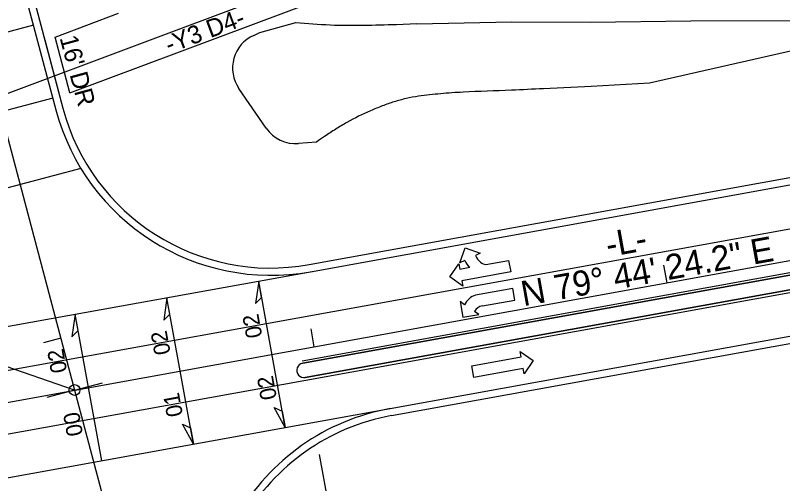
# Model space of a CAD drawing. Extents: x 1616561 to 1622460, y 896726 to 899651.
# Drawn here: x 1620937.7 to 1621151.6, y 898090.7 to 898221.3 of the extents above; entities that cross this region are included whole.
import ezdxf

# ---------------------------------------------------------------- set-up
doc = ezdxf.new("R2010")
doc.units = 0
for name, color, linetype in [('Exist Boundary Study Area', 7, 'Continuous'), ('Old_Level_3', 7, 'Continuous'), ('Prop Conc Drive Radius Type', 7, 'Continuous'), ('Prop Dimension', 7, 'Continuous'), ('Prop Horizontal Alignment Tick Small', 7, 'Continuous'), ('Prop Lane Arrow CELL', 7, 'Continuous'), ('Prop North Arrow NAD83 for Plan Sheets CELL', 7, 'Continuous'), ('Prop Rem of Exist Asph Pvmt', 7, 'Continuous'), ('Prop Shade Medium', 7, 'Continuous'), ('Prop Superelevation  Arrow CELL', 7, 'Continuous'), ('Prop Superelevation Label', 7, 'Continuous'), ('Prop Terminator CELL', 7, 'Continuous'), ('Scratch_Level_1', 7, 'Continuous'), ('Sheet Cutting Line CELL', 7, 'Continuous'), ('Sheet North Arrow CELL', 7, 'Continuous'), ('Sheet Sticker Preliminary CELL', 7, 'Continuous')]:
    doc.layers.add(name, color=color, linetype=linetype)

msp = doc.modelspace()

# ---------------------------------------------------------------- linework, layer by layer
at = {"layer": 'Exist Boundary Study Area'}
for p, q in [((1621017.81, 898124.3), (1621165.41, 898151.01)), ((1621166.12, 898147.08), (1621018.52, 898120.36))]:
    msp.add_line(p, q, dxfattribs=at)
msp.add_arc((1621018.16, 898122.33), 2, 100.2599, 280.2599, dxfattribs=at)
at = {"layer": 'Old_Level_3'}
for p, q in [((1620903.36, 898116.54), (1621261.54, 898181.37)), ((1621017.67, 898125.03), (1621165.28, 898151.75)), ((1620870.63, 898122.84), (1621020.48, 898149.94)), ((1621018.65, 898119.62), (1621166.26, 898146.34)), ((1620891.42, 898096.59), (1621018.65, 898119.62)), ((1620893.24, 898084.73), (1621042.18, 898111.69))]:
    msp.add_line(p, q, dxfattribs=at)
at = {"layer": 'Prop Conc Drive Radius Type'}
msp.add_line((1620945.86, 898214.48), (1620949.99, 898198.94), dxfattribs=at)
at = {"layer": 'Prop Dimension'}
msp.add_line((1621022.41, 898098.88), (1621037.62, 898014.84), dxfattribs=at)
at = {"layer": 'Prop Horizontal Alignment Tick Small'}
for p, q in [((1620941.12, 898232.34), (1620950.92, 898195.46)), ((1621019.59, 898151.82), (1621369.62, 898215.16)), ((1621042.54, 898109.72), (1621403.81, 898175.11))]:
    msp.add_line(p, q, dxfattribs=at)
for centre, start, end in [((1621008.91, 898210.86), 194.8727, 280.2581), ((1621053.22, 898050.68), 100.2599, 199.8507)]:
    msp.add_arc(centre, 60, start, end, dxfattribs=at)
at = {"layer": 'Prop Lane Arrow CELL'}
for p, q in [((1621061.63, 898152.28), (1621063.11, 898156.46)), ((1621063.11, 898156.46), (1621067.29, 898154.98)), ((1621067.29, 898154.98), (1621065.98, 898154.34)), ((1621058.88, 898148.38), (1621061.37, 898152.03)), ((1621061.37, 898152.03), (1621061.64, 898150.56)), ((1621062.98, 898152.93), (1621061.63, 898152.28)), ((1621068.87, 898151.87), (1621075.22, 898153.01)), ((1621075.22, 898153.01), (1621075.8, 898149.77)), ((1621061.64, 898150.56), (1621064.44, 898151.06)), ((1621075.8, 898149.77), (1621062.22, 898147.31)), ((1621062.49, 898145.83), (1621058.88, 898148.38)), ((1621062.22, 898147.31), (1621062.49, 898145.83)), ((1621076.38, 898145.13), (1621065.99, 898143.3)), ((1621076.96, 898141.88), (1621076.38, 898145.13)), ((1621062.96, 898140.63), (1621061.74, 898141.49)), ((1621061.74, 898141.49), (1621062.46, 898137.14)), ((1621067.94, 898140.29), (1621076.96, 898141.88)), ((1621066.9, 898137.88), (1621065.68, 898138.73)), ((1621062.46, 898137.14), (1621066.9, 898137.88)), ((1621064.94, 898123.6), (1621078.72, 898126.09)), ((1621078.72, 898126.09), (1621078.45, 898127.57)), ((1621078.45, 898127.57), (1621082.1, 898125.08)), ((1621065.53, 898120.35), (1621064.94, 898123.6)), ((1621082.1, 898125.08), (1621079.57, 898121.37)), ((1621079.3, 898122.84), (1621065.53, 898120.35)), ((1621079.57, 898121.37), (1621079.3, 898122.84))]:
    msp.add_line(p, q, dxfattribs=at)
for centre, radius, start, end in [((1621070.1, 898156), 4.43, 201.9696, 232.8232), ((1621067.11, 898154.59), 4.43, 201.8508, 232.7294), ((1621069.06, 898154.38), 2.52, 229.3331, 265.6451), ((1621067.67, 898138.34), 5.25, 108.6553, 153.967), ((1621068.5, 898137.08), 3.28, 99.9792, 149.6374)]:
    msp.add_arc(centre, radius, start, end, dxfattribs=at)
at = {"layer": 'Prop North Arrow NAD83 for Plan Sheets CELL'}
for points in [[(1621005.53, 898147.23), (1621004.63, 898140.97), (1621006.35, 898142.67)], [(1620979.94, 898142.59), (1620979.04, 898136.33), (1620980.77, 898138.04)], [(1620954.36, 898137.96), (1620953.46, 898131.7), (1620955.18, 898133.41)], [(1621012.92, 898106.39), (1621009.88, 898111.94), (1621012.1, 898110.94)], [(1620987.34, 898101.76), (1620984.3, 898107.31), (1620986.51, 898106.31)]]:
    msp.add_lwpolyline(points, close=True, dxfattribs=at)
at = {"layer": 'Prop Rem of Exist Asph Pvmt'}
for p, q in [((1621005.86, 898216.5), (1621015.87, 898219.32)), ((1621004.16, 898215.74), (1621005.86, 898216.5)), ((1621158.38, 898212.33), (1621114.48, 898202.38)), ((1621007.59, 898189.88), (1621000, 898200.96)), ((1621021.66, 898185.97), (1621016.66, 898185.56))]:
    msp.add_line(p, q, dxfattribs=at)
for points in [[(1621043.99, 898218.8), (1621049.6, 898219.01), (1621049.67, 898218.95), (1621076, 898219.52), (1621098.08, 898219.37), (1621126.06, 898219.76), (1621167.41, 898219.86), (1621208.75, 898220.77), (1621226.84, 898221.26)], [(1621114.48, 898202.38), (1621098.22, 898201.46), (1621084.97, 898200.86)]]:
    msp.add_lwpolyline(points, dxfattribs=at)
for centre, start, end in [((1621008.25, 898206.61), 114.124, 214.414), ((1621015.84, 898195.53), 214.414, 274.7054)]:
    msp.add_arc(centre, 10, start, end, dxfattribs=at)
for points in [[(1621015.87, 898219.32), (1621025.49, 898218.66), (1621043.99, 898218.8)], [(1621084.97, 898200.86), (1621075.99, 898200.43), (1621062.54, 898199.89), (1621059.42, 898199.71), (1621056.3, 898199.45), (1621053.19, 898199.13), (1621050.08, 898198.74), (1621046.66, 898198.11), (1621043.31, 898197.2), (1621040.01, 898196.05), (1621038.37, 898195.4), (1621036.74, 898194.72), (1621030.16, 898191.46), (1621027.02, 898189.59), (1621023.93, 898187.58), (1621021.66, 898185.97)]]:
    msp.add_spline(points, degree=3, dxfattribs=at)
at = {"layer": 'Prop Shade Medium'}
for p, q in [((1621165.41, 898151.01), (1621017.81, 898124.3)), ((1621018.52, 898120.36), (1621166.12, 898147.08))]:
    msp.add_line(p, q, dxfattribs=at)
msp.add_arc((1621018.16, 898122.33), 2, 100.2599, 280.2599, dxfattribs=at)
at = {"layer": 'Prop Superelevation  Arrow CELL'}
for p, q in [((1621119.43, 898146.76), (1621118.54, 898151.68)), ((1621021.03, 898128.94), (1621020.14, 898133.87)), ((1620950.36, 898131.33), (1620945.53, 898130.04))]:
    msp.add_line(p, q, dxfattribs=at)
at = {"layer": 'Prop Superelevation Label'}
for q in [(1620961.94, 898118.9), (1620946.47, 898114.79)]:
    msp.add_line((1620954.2, 898116.85), q, dxfattribs=at)
at = {"layer": 'Prop Terminator CELL'}
for p, q in [((1620952.89, 898199.71), (1621051.69, 898236.7)), ((1620939.19, 898231.83), (1620948.98, 898194.94)), ((1620948.77, 898215.25), (1620966.48, 898221.88)), ((1620952.89, 898199.71), (1620948.77, 898215.25)), ((1621019.95, 898149.85), (1621369.97, 898213.19)), ((1621042.18, 898111.69), (1621403.45, 898177.08))]:
    msp.add_line(p, q, dxfattribs=at)
for centre, start, end in [((1621008.91, 898210.86), 194.8727, 280.2581), ((1621053.22, 898050.68), 100.2599, 199.8507)]:
    msp.add_arc(centre, 62, start, end, dxfattribs=at)
at = {"layer": 'Sheet Cutting Line CELL'}
for p, q in [((1620903.06, 898309.43), (1620954.2, 898116.85)), ((1620932.52, 898198.49), (1621073, 898251.08)), ((1620889.86, 898105.2), (1621477.45, 898211.56)), ((1620954.2, 898116.85), (1620966.99, 898068.72))]:
    msp.add_line(p, q, dxfattribs=at)
at = {"layer": 'Sheet North Arrow CELL'}
msp.add_line((1620954.2, 898116.85), (1620693.65, 898206.85), dxfattribs=at)
msp.add_circle((1620954.2, 898116.85), 1.5, dxfattribs=at)
at = {"layer": 'Sheet Sticker Preliminary CELL'}
for p, q in [((1620942.71, 898218.57), (1620914.12, 898210.98)), ((1620948.1, 898198.27), (1620918.47, 898190.4)), ((1620955.94, 898178.63), (1620917.01, 898168.28)), ((1621012.92, 898106.39), (1621005.53, 898147.23)), ((1620983.64, 898122.18), (1620979.94, 898142.59)), ((1620958.06, 898117.55), (1620954.36, 898137.96)), ((1620987.34, 898101.76), (1620983.64, 898122.18)), ((1620961.75, 898097.13), (1620958.06, 898117.55))]:
    msp.add_line(p, q, dxfattribs=at)

# ---------------------------------------------------------------- texts
at = {"layer": 'Prop Dimension'}
msp.add_text("16' DR", height=5, rotation=285.1876, dxfattribs=at).set_placement((1620950, 898215.04))
at = {"layer": 'Scratch_Level_1'}
for s, height, rotation, p in [('-Y3 D4-', 5, 20.5237, (1620980.56, 898210.65)), ('-L-', 7, 10.2599, (1621102.97, 898153.87)), ('N 79%%d 44\' 24.2" E', 7, 10.2599, (1621079.37, 898140.2))]:
    msp.add_text(s, height=height, rotation=rotation, dxfattribs=at).set_placement(p)
at = {"layer": 'Sheet Sticker Preliminary CELL'}
for s, p in [('02', (1621006.58, 898131.76)), ('02', (1620981, 898127.08)), ('02', (1620952.15, 898122.02)), ('02', (1621010.64, 898114.54)), ('01', (1620984.44, 898109.81)), ('00', (1620956.59, 898104.41))]:
    msp.add_text(s, height=4.5, rotation=100.2599, dxfattribs=at).set_placement(p)

doc.saveas('drawing.dxf')
